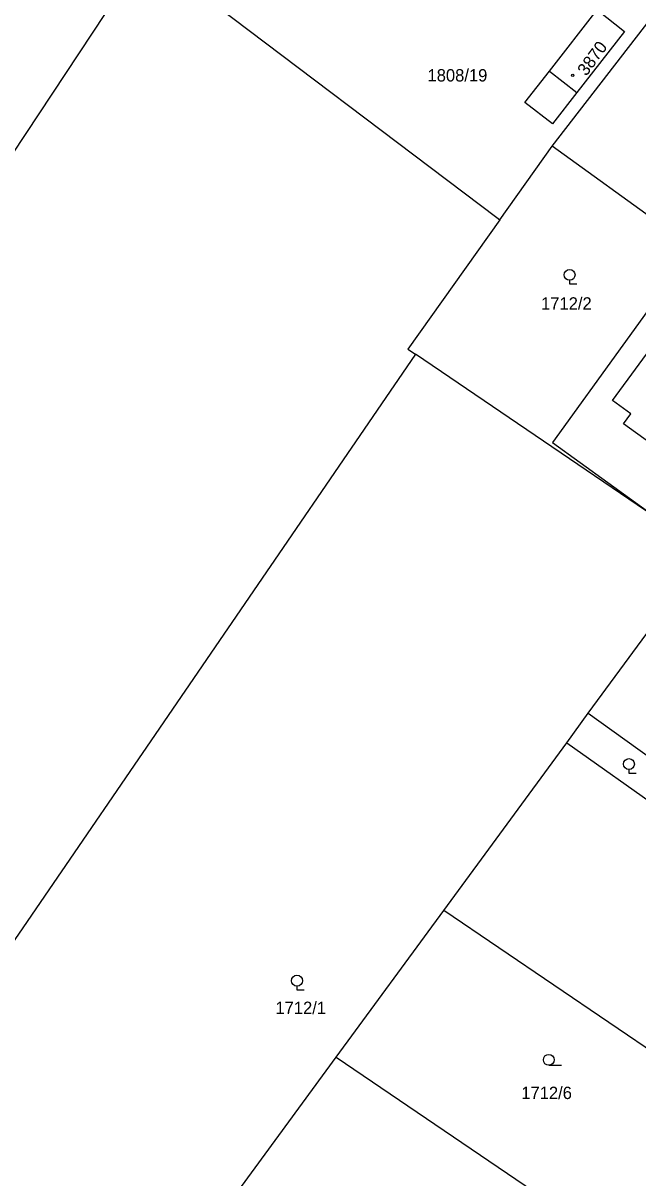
# Model space of a CAD drawing. Extents: x -679220 to -673243, y -1075091 to -1066557.
# Drawn here: x -677246.9 to -677162.5, y -1072386.3 to -1072227.6 of the extents above; entities that cross this region are included whole.
import ezdxf

# ---------------------------------------------------------------- set-up
doc = ezdxf.new("R2010")
doc.units = 0
for name, color, linetype in [('Hranice parcel', 7, 'Continuous'), ('Parcelní čísla', 7, 'Continuous'), ('Vnitřní kresba', 7, 'Continuous'), ('Značky budov', 7, 'Continuous'), ('Značky kultur', 7, 'Continuous')]:
    doc.layers.add(name, color=color, linetype=linetype)

msp = doc.modelspace()

# ---------------------------------------------------------------- linework, layer by layer
at = {"layer": 'Hranice parcel'}
for p, q in [((-677174.28, -1072244.49), (-677154.6, -1072218.99)), ((-677181.46, -1072254.61), (-677174.28, -1072244.49)), ((-677154.92, -1072258.47), (-677174.28, -1072244.49)), ((-677193.06, -1072273.1), (-677289.2, -1072413.6)), ((-677159.03, -1072296.2), (-677193.06, -1072273.1)), ((-677172.27, -1072326.49), (-677169.31, -1072322.45)), ((-677169.31, -1072322.45), (-677149.08, -1072337.02)), ((-677189.16, -1072349.55), (-677172.27, -1072326.49)), ((-677172.27, -1072326.49), (-677151.99, -1072340.91)), ((-677203.94, -1072369.73), (-677189.16, -1072349.55)), ((-677150.5, -1072375.83), (-677189.16, -1072349.55)), ((-677216.96, -1072387.5), (-677203.94, -1072369.73)), ((-677203.94, -1072369.73), (-677165.72, -1072395.65))]:
    msp.add_line(p, q, dxfattribs=at)
for points in [[(-677230.11, -1072217.83), (-677272.35, -1072281.68), (-677290.69, -1072268.69)], [(-677225.07, -1072221.64), (-677181.86, -1072254.31), (-677181.46, -1072254.61)], [(-677170.88, -1072237.13), (-677174.22, -1072241.43), (-677178, -1072238.5), (-677174.65, -1072234.2), (-677168.09, -1072225.77), (-677164.31, -1072228.71), (-677170.88, -1072237.13)], [(-677181.46, -1072254.61), (-677194.09, -1072272.4), (-677193.06, -1072273.1)], [(-677154.92, -1072258.47), (-677174.23, -1072285.22), (-677159.03, -1072296.2)], [(-677165.96, -1072279.43), (-677159.18, -1072270.13), (-677158.81, -1072270.39), (-677156.45, -1072267.15), (-677150.76, -1072271.3), (-677153.05, -1072274.53), (-677150.59, -1072276.39), (-677152.66, -1072279.19), (-677151.05, -1072280.37), (-677153.1, -1072283.2), (-677154.73, -1072282.09), (-677157.33, -1072285.68), (-677159.83, -1072283.85), (-677160.87, -1072285.28), (-677164.47, -1072282.66), (-677163.44, -1072281.26), (-677165.96, -1072279.43)], [(-677169.31, -1072322.45), (-677153.83, -1072301.4), (-677152.92, -1072300.07)]]:
    msp.add_lwpolyline(points, dxfattribs=at)
at = {"layer": 'Vnitřní kresba'}
msp.add_line((-677174.65, -1072234.2), (-677170.88, -1072237.13), dxfattribs=at)
at = {"layer": 'Značky budov'}
msp.add_circle((-677171.45, -1072234.75), 0.175, dxfattribs=at)
at = {"layer": 'Značky kultur'}
for p, q in [((-677171.87, -1072262.93), (-677171.87, -1072263.43)), ((-677171.87, -1072263.43), (-677170.87, -1072263.43)), ((-677163.72, -1072330.17), (-677163.72, -1072330.67)), ((-677163.72, -1072330.67), (-677162.72, -1072330.67)), ((-677209.32, -1072359.95), (-677209.32, -1072360.45)), ((-677209.32, -1072360.45), (-677208.32, -1072360.45)), ((-677174.73, -1072370.83), (-677172.98, -1072370.83))]:
    msp.add_line(p, q, dxfattribs=at)
for centre in [(-677171.87, -1072262.18), (-677163.72, -1072329.42), (-677209.32, -1072359.2), (-677174.73, -1072370.08)]:
    msp.add_circle(centre, 0.75, dxfattribs=at)

# ---------------------------------------------------------------- texts
at = {"layer": 'Parcelní čísla'}
msp.add_text('3870', height=1.7, rotation=54, dxfattribs=at).set_placement((-677169.57, -1072234.95))
for s, p in [('1808/19', (-677191.39, -1072235.6)), ('1712/2', (-677175.79, -1072266.96)), ('1712/1', (-677212.28, -1072363.78)), ('1712/6', (-677178.51, -1072375.47))]:
    msp.add_text(s, height=1.7, dxfattribs=at).set_placement(p)

doc.saveas('drawing.dxf')
